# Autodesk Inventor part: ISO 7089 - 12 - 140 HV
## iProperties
Author: Tobben
Created: 2001-12
Part Number: ISO 7089 - 12 - 140 HV
Catalog Web Link: file:///F:/Cad/Autodesk/Inventor 5/Content/Iso/index.htm?doNavigateId=8E0024B3-6CA5-42D3-99D9-F0092A40B40C|74B1A93DC0A940FBB961F80085F4CFD|true
Description: Washer
Document SubType Name: Standard Catalog Part
Standard: ISO 7089 - 12 - 140 HV
Designer: Tobben
CLASSIFICATION: 31161807 un/spsc
MANUFACTURER: ISO Standard System
Control State: 0
Master: False
Checked Out: False
PropertySet Name: Design Tracking Control
Shininess: 64.0
Angle Display Precision: 2
Document Length Units: 11269
Document Angle Units: 11283
Document Time Units: 11279
Document Mass Units: 11290
Document Length Units Precision: 3
Document Angle Units Precision: 2
Compacted: True
PropertySet Name: _Private Model Information
Density: 0.0
Volumn: 0.0
Area: 0.0
PropertySet Name: Model Information
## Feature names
1. Base1
